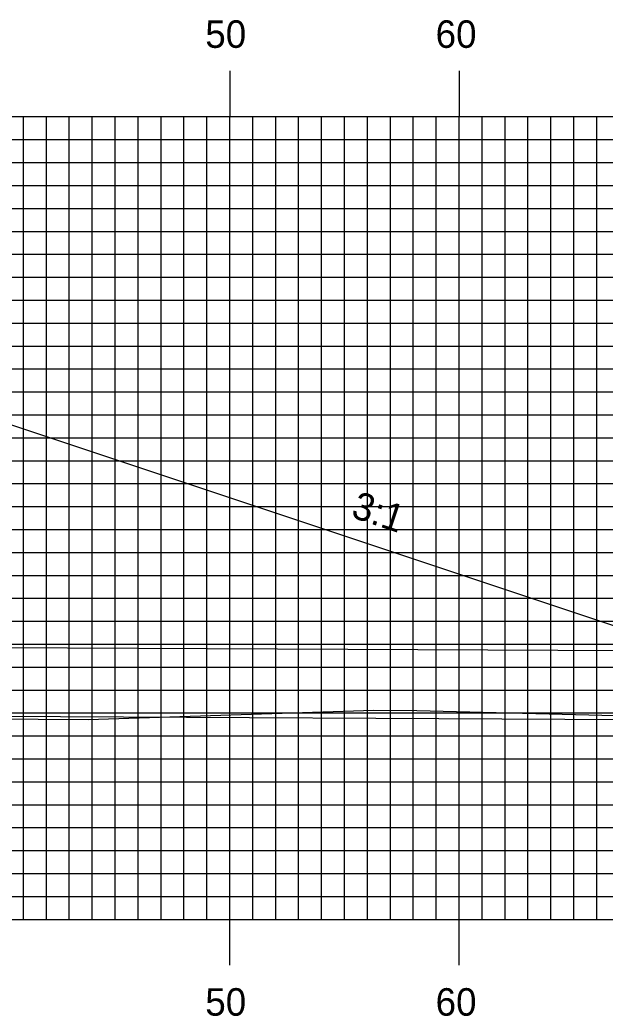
# Model space of a CAD drawing. Extents: x 1781467 to 1781810, y 442591 to 442811.
# Drawn here: x 1781673.25 to 1781698.77, y 442714.45 to 442757.88 of the extents above; entities that cross this region are included whole.
import ezdxf

# ---------------------------------------------------------------- set-up
doc = ezdxf.new("R2010")
doc.units = 0
for name, color, linetype in [('ANNOTATION', 7, 'Continuous'), ('D_Drainage_Culvert', 7, 'Continuous'), ('D_Roadway_Centerline', 7, 'Continuous'), ('D_Roadway_SlopeLines', 7, 'Continuous'), ('H_V ANNOTATION', 7, 'Continuous'), ('MAJOR', 7, 'Continuous'), ('MINOR', 7, 'Continuous'), ('S_Roadway_Centerline', 7, 'Continuous')]:
    doc.layers.add(name, color=color, linetype=linetype)

msp = doc.modelspace()

# ---------------------------------------------------------------- linework, layer by layer
at = {"layer": 'D_Drainage_Culvert'}
for p, q in [((1781559.423, 442731.106), (1781707.417, 442730.343)), ((1781559.423, 442731.106), (1781707.417, 442730.343)), ((1781559.408, 442728.106), (1781707.402, 442727.343)), ((1781559.408, 442728.106), (1781707.402, 442727.343))]:
    msp.add_line(p, q, dxfattribs=at)
at = {"layer": 'D_Roadway_Centerline'}
msp.add_lwpolyline([(1781664.408, 442743.053), (1781699.132, 442731.478)], dxfattribs=at)
at = {"layer": 'D_Roadway_SlopeLines'}
msp.add_lwpolyline([(1781652.408, 442746.053), (1781664.408, 442743.053), (1781694.17, 442733.132)], dxfattribs=at)
at = {"layer": 'MAJOR'}
for p, q in [((1781682.408, 442755.669), (1781682.408, 442753.665)), ((1781692.408, 442755.669), (1781692.408, 442753.665)), ((1781492.408, 442753.665), (1781772.408, 442753.665)), ((1781492.408, 442753.665), (1781772.408, 442753.665)), ((1781682.408, 442718.665), (1781682.408, 442753.665)), ((1781692.408, 442718.665), (1781692.408, 442753.665)), ((1781492.408, 442748.665), (1781772.408, 442748.665)), ((1781492.408, 442743.665), (1781772.408, 442743.665)), ((1781492.408, 442738.665), (1781772.408, 442738.665)), ((1781492.408, 442733.665), (1781772.408, 442733.665)), ((1781492.408, 442728.665), (1781772.408, 442728.665)), ((1781492.408, 442723.665), (1781772.408, 442723.665)), ((1781492.408, 442718.665), (1781772.408, 442718.665)), ((1781492.408, 442718.665), (1781772.408, 442718.665)), ((1781682.408, 442716.661), (1781682.408, 442718.665)), ((1781692.408, 442716.661), (1781692.408, 442718.665))]:
    msp.add_line(p, q, dxfattribs=at)
at = {"layer": 'MINOR'}
for p, q in [((1781673.408, 442718.665), (1781673.408, 442753.665)), ((1781674.408, 442718.665), (1781674.408, 442753.665)), ((1781675.408, 442718.665), (1781675.408, 442753.665)), ((1781676.408, 442718.665), (1781676.408, 442753.665)), ((1781677.408, 442718.665), (1781677.408, 442753.665)), ((1781678.408, 442718.665), (1781678.408, 442753.665)), ((1781679.408, 442718.665), (1781679.408, 442753.665)), ((1781680.408, 442718.665), (1781680.408, 442753.665)), ((1781681.408, 442718.665), (1781681.408, 442753.665)), ((1781683.408, 442718.665), (1781683.408, 442753.665)), ((1781684.408, 442718.665), (1781684.408, 442753.665)), ((1781685.408, 442718.665), (1781685.408, 442753.665)), ((1781686.408, 442718.665), (1781686.408, 442753.665)), ((1781687.408, 442718.665), (1781687.408, 442753.665)), ((1781688.408, 442718.665), (1781688.408, 442753.665)), ((1781689.408, 442718.665), (1781689.408, 442753.665)), ((1781690.408, 442718.665), (1781690.408, 442753.665)), ((1781691.408, 442718.665), (1781691.408, 442753.665)), ((1781693.408, 442718.665), (1781693.408, 442753.665)), ((1781694.408, 442718.665), (1781694.408, 442753.665)), ((1781695.408, 442718.665), (1781695.408, 442753.665)), ((1781696.408, 442718.665), (1781696.408, 442753.665)), ((1781697.408, 442718.665), (1781697.408, 442753.665)), ((1781698.408, 442718.665), (1781698.408, 442753.665)), ((1781492.408, 442752.665), (1781772.408, 442752.665)), ((1781492.408, 442751.665), (1781772.408, 442751.665)), ((1781492.408, 442750.665), (1781772.408, 442750.665)), ((1781492.408, 442749.665), (1781772.408, 442749.665)), ((1781492.408, 442747.665), (1781772.408, 442747.665)), ((1781492.408, 442746.665), (1781772.408, 442746.665)), ((1781492.408, 442745.665), (1781772.408, 442745.665)), ((1781492.408, 442744.665), (1781772.408, 442744.665)), ((1781492.408, 442742.665), (1781772.408, 442742.665)), ((1781492.408, 442741.665), (1781772.408, 442741.665)), ((1781492.408, 442740.665), (1781772.408, 442740.665)), ((1781492.408, 442739.665), (1781772.408, 442739.665)), ((1781492.408, 442737.665), (1781772.408, 442737.665)), ((1781492.408, 442736.665), (1781772.408, 442736.665)), ((1781492.408, 442735.665), (1781772.408, 442735.665)), ((1781492.408, 442734.665), (1781772.408, 442734.665)), ((1781492.408, 442732.665), (1781772.408, 442732.665)), ((1781492.408, 442731.665), (1781772.408, 442731.665)), ((1781492.408, 442730.665), (1781772.408, 442730.665)), ((1781492.408, 442729.665), (1781772.408, 442729.665)), ((1781492.408, 442727.665), (1781772.408, 442727.665)), ((1781492.408, 442726.665), (1781772.408, 442726.665)), ((1781492.408, 442725.665), (1781772.408, 442725.665)), ((1781492.408, 442724.665), (1781772.408, 442724.665)), ((1781492.408, 442722.665), (1781772.408, 442722.665)), ((1781492.408, 442721.665), (1781772.408, 442721.665)), ((1781492.408, 442720.665), (1781772.408, 442720.665)), ((1781492.408, 442719.665), (1781772.408, 442719.665))]:
    msp.add_line(p, q, dxfattribs=at)
at = {"layer": 'S_Roadway_Centerline'}
msp.add_lwpolyline([(1781593.87, 442727.964), (1781606.484, 442727.726), (1781617.857, 442727.475), (1781620.123, 442727.438), (1781641.461, 442727.297), (1781641.85, 442727.295), (1781642.284, 442727.296), (1781664.583, 442727.453), (1781665.292, 442727.459), (1781676.236, 442727.377), (1781688.684, 442727.785), (1781690.563, 442727.773), (1781710.171, 442727.271), (1781711.233, 442727.279), (1781712.294, 442727.326), (1781733.343, 442727.578), (1781736.005, 442727.516), (1781754.54, 442727.304), (1781758.146, 442727.362), (1781769.134, 442727.637), (1781772.408, 442727.637)], dxfattribs=at)

# ---------------------------------------------------------------- texts
at = {"layer": 'ANNOTATION'}
msp.add_text('3:1', height=1.2, rotation=341.5652, dxfattribs=at).set_placement((1781687.644, 442736.216))
at = {"layer": 'H_V ANNOTATION'}
for s, p in [('50', (1781681.337, 442756.665)), ('60', (1781691.38, 442756.665)), ('50', (1781681.337, 442714.465)), ('60', (1781691.38, 442714.465))]:
    msp.add_text(s, height=1.2, dxfattribs=at).set_placement(p)

doc.saveas('drawing.dxf')
